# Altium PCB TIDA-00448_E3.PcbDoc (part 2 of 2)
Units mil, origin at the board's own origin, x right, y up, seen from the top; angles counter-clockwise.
Board outline 2125 x 2550 mil, 4 copper layers (Top Layer, MidLayer1, MidLayer2, Bottom Layer), stack 90 mil thick; 140 components, 62 nets, 330 pads, 116 vias.
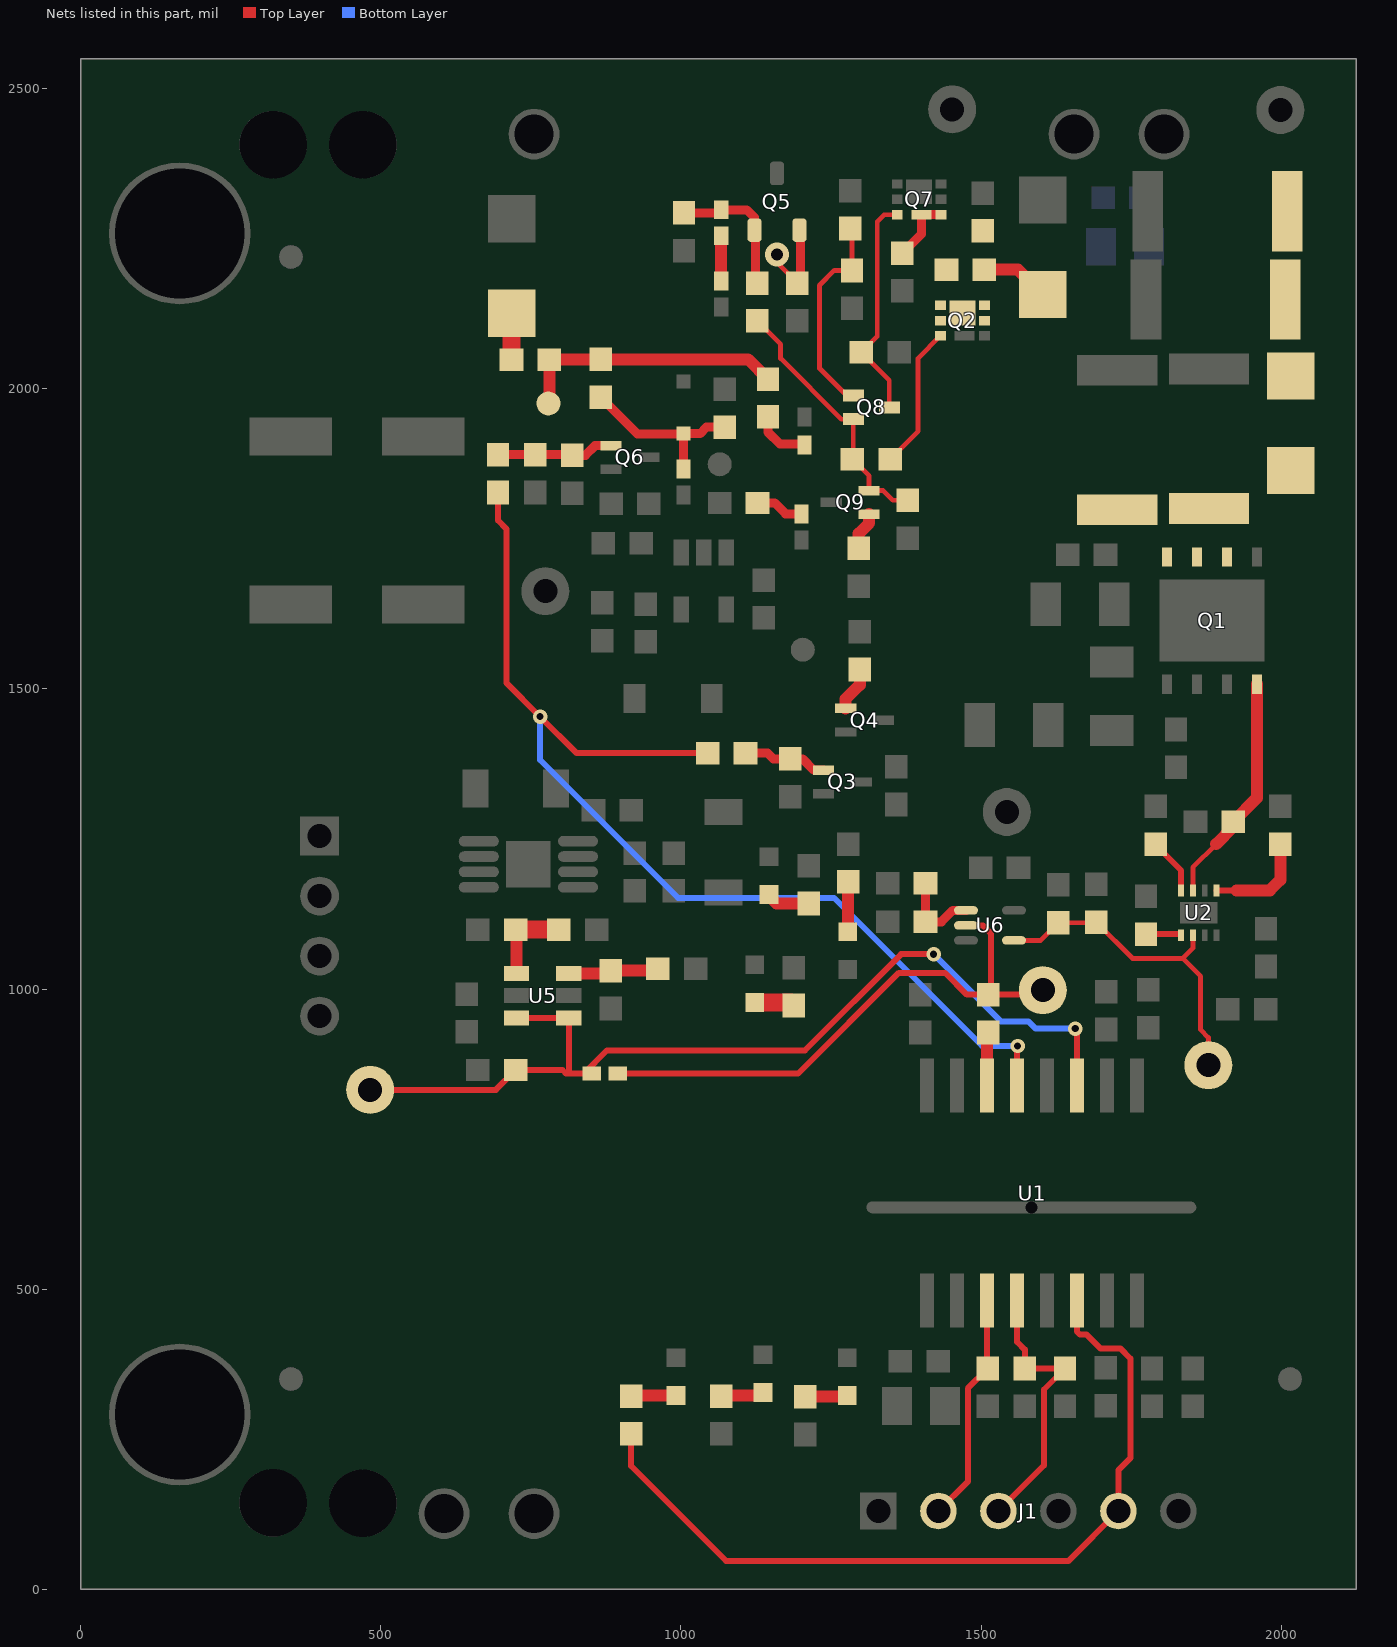
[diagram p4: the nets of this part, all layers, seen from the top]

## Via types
v1: diameter 30, hole 16, Top Layer to Bottom Layer, tented both sides, 89 vias
v2: diameter 24, hole 12, Top Layer to Bottom Layer, 26 vias
v3: diameter 40, hole 20, Top Layer to Bottom Layer, 1 vias

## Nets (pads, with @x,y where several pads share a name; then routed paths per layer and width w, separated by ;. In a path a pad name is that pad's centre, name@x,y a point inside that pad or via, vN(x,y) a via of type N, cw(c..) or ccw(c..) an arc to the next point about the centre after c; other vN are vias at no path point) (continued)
NetC24_2: C24.2 Q6.1 R15.2 R39.1 | length 195.6
  Top Layer w15: R15.2@695,1890.5 R39.1@757,1890.5 818,1890.5 C24.2@819,1889.5 840.5,1889.5 856.68,1905.68 Q6.1@883.5,1905.68
NetC39_1: C39.1 D7.2 Q5.1 R13.1 | length 235.2
  Top Layer w15: C39.1@1005,2293.5 1061.84,2293.5 D7.2@1067,2298.65 1109.35,2298.65 1122.6,2285.4 Q5.1@1122.6,2264.76 ; Q5.1@1124.6,2264.76 1124.6,2258.76 1124.5,2258.66 1124.5,2179 R13.1@1127,2176.5
NetC41_2: C41.2 R60.2 U6.1 | length 139.4
  Top Layer w15: R60.2@1407.5,1176 C41.2@1407.5,1112 1434,1112 1453,1131 U6.1@1475,1131
NetD1_2: D1.2 R2.2 R58.2
NetD2_2: D2.2 R6.1 | length 77.5
  Top Layer w30: R6.1@717.5,2049 717.5,2125.76 D2.2@718,2126.26
NetD5_2: D5.2 D20.1 R9.1 R11.2 | length 296.8
  Top Layer w15: R9.1@866,1986.5 927.81,1924.69 D20.1@1000,1924.69 ; D5.2@1004,1866.65 1004,1920.69 D20.1@1000,1924.69 ; D20.1@1004,1924.69 D20.1@1000,1924.69 ; D20.1@1004,1925.69 1031.69,1925.69 1042.5,1936.5 R11.2@1073,1936.5
NetD6_1: D6.1 R14.2 | length 81.1
  Top Layer w15: R14.2@1127.5,1810 1156,1810 1174.35,1791.65 D6.1@1201,1791.65
NetD7_1: D7.1 D17.2 | length 75.7
  Top Layer w20: D17.2@1067,2179.65 D7.1@1067,2255.35
NetD9_1: D9.1 R42.2 | length 76.2
  Top Layer w20: D9.1@1143,1157.5 1144.5,1157.5 1159.5,1142.5 R42.2@1213,1142.5
NetD10_1: D10.1 R43.1 | length 67.1
  Top Layer w30: D10.1@1123,977.5 1183,977.5 R43.1@1188,972.5
NetD11_1: D11.1 R44.2 | length 83.4
  Top Layer w20: D11.1@1278,1095.5 1278,1177.5 R44.2@1279,1178.5
NetD12_1: D12.1 R45.2 | length 70.8
  Top Layer w20: R45.2@1207,320.5 1274.99,320.5 D12.1@1277,322.5
NetD13_1: D13.1 R46.2 | length 75
  Top Layer w20: R46.2@917,322.5 D13.1@992,322.5
NetD14_1: D14.1 R47.2 | length 72.1
  Top Layer w20: R47.2@1067,322.5 1132,322.5 D14.1@1137,327.5
NetD18_2: D18.2 R31.2 | length 114.8
  Top Layer w20: R31.2@1505.5,2199 1561.26,2199 D18.2@1603,2157.26
NetQ2_1: Q2.1 Q2.2 Q2.5 Q2.6 Q2.8 R5.1 R31.1
NetQ2_3: Q2.3 R59.1 | length 240.2
  Top Layer w8: R59.1@1348.5,1883 1395.18,1929.69 1395.18,2051.2 Q2.3@1432.39,2088.41
NetQ3_1: Q3.1 R52.2 R53.1 | length 141.7
  Top Layer w15: R52.2@1107.5,1393 1144.46,1393 1153.96,1383.5 R53.1@1182,1383.5 1202.5,1383.5 1221.32,1364.68 Q3.1@1237.5,1364.68
NetQ4_1: Q4.1 R10.2 | length 74.6
  Top Layer w20: Q4.1@1274.5,1467.68 1274.5,1483.5 1298,1507 R10.2@1298,1532.5
NetQ5_2: Q5.2 R16.2 | length 146.1
  Top Layer w8: v3(1160,2224) 1166,2218 1166,2204.5 R16.2@1194,2176.5
  Top Layer w15: R16.2@1194,2176.5 1199.4,2181.9 Q5.2@1199.4,2258.76
NetQ7_3: Q7.3 Q8.3 R17.2 | length 378
  Top Layer w8: Q8.3@1347.2,1969.4 1347.2,2014.3 R17.2@1300.5,2061 1327,2087.5 1327,2279 1338.41,2290.41 Q7.3@1360.39,2290.41
NetQ7_4: Q7.4 Q7.7 R50.2 | length 109.9
  Top Layer w15: R50.2@1369,2226.5 1400.74,2258.24 Q7.7@1400.74,2290.41 Q7.4@1433.61,2290.41
NetQ8_1: Q8.1 R18.2 R19.2 | length 349.3
  Top Layer w8: R18.2@1282,2267.5 1285,2264.5 R19.2@1285,2197.5 1255.5,2197.5 1230.82,2172.82 1230.82,2034.18 1275.9,1989.1 Q8.1@1287.2,1989.1
NetQ8_2: Q8.2 Q9.2 R13.2 R32.2 R59.2 | length 444.4
  Top Layer w8: R13.2@1127,2113.5 1166,2074.5 1166,2050.85 1267.15,1949.7 Q8.2@1287.2,1949.7 1287.2,1884.7 R59.2@1285.5,1883 1313.5,1855.01 Q9.2@1313.5,1830.69 1337.05,1830.69 1353.24,1814.5 R32.2@1378,1814.5
NetQ9_1: Q9.1 R51.2 | length 64.1
  Top Layer w20: R51.2@1296,1734.5 1296,1759 1313.5,1776.5 Q9.1@1313.5,1791.32
NetR1_2: R1.2 U2.1 | length 59.3
  Top Layer w10: R1.2@1775,1091.5 1831.57,1091.5 U2.1@1833.47,1089.6
NetR6_2: R6.2 R8.2 R9.2 TP5.1 | length 452
  Top Layer w20: TP5.1@779,1976 780.5,1977.5 R6.2@780.5,2049 865.5,2049 R9.2@866,2049.5 1112,2049.5 R8.2@1145,2016.5
NetR8_1: R8.1 R34.2 | length 94.6
  Top Layer w15: R8.1@1145,1953.5 1145,1928 1164.65,1908.35 R34.2@1206,1908.35
NetR22_1: R22.1 U2.8 | length 94.7
  Top Layer w10: R22.1@1791,1241.5 1791,1240 1833.47,1197.53 U2.8@1833.47,1164.4
NetR26_1: R26.1 U2.5 | length 173.3
  Top Layer w10: U2.5@1892.53,1164.4 1925.4,1164.4
  Top Layer w20: 1925.4,1164.4 1981.4,1164.4 1999,1182 R26.1@1999,1241.5
NetR33_1: R33.1 R36.2 U5.4 | length 145.6
  Top Layer w20: U5.4@726,1026 R33.1@726,1097.5
  Top Layer w30: R33.1@726,1097.5 R33.1@724.5,1099 R36.2@796.5,1099
NetR35_1: R35.1 R37.2 U5.3 | length 151.8
  Top Layer w20: U5.3@813,1026 878.5,1026 R37.2@883,1030.5 958,1030.5 R35.1@961.5,1034
NetR41_2: R41.2 U1.14 | length 89.2
  Top Layer w20: U1.14@1510,839.13 1510,925.5 R41.2@1512,927.5
PWM: J1.2 R23.1 U1.3 | length 383.8
  Top Layer w10: J1.2@1429,130 1478,179 1478,334.5 R23.1@1511,367.5 ; R23.1@1510,368.5 U1.3@1510,480.87
PWM-ISO: D8.2 R41.1 TP10.1 U6.2 | length 947.5
  Top Layer w10: D8.2@894.65,859 1195,859 1363,1027 1440,1027 1476.5,990.5 R41.1@1512,990.5 ; U6.2@1475,1106 1503,1106 1517,1092 1517,995.5 R41.1@1512,990.5 ; TP10.1@1603,998 1595.5,990.5 R41.1@1512,990.5
PWM_BUF: R56.2 R57.1 TP9.1 U2.2 U6.4 | length 560.2
  Top Layer w8: U6.4@1555,1081 1599.5,1081 R57.1@1629,1110.5 1691,1110.5 R56.2@1692,1111.5 1752.5,1051 1836,1051 ; U2.2@1853.16,1089.6 1853.16,1068.16 1836,1051 ; TP9.1@1879,873 1879,919 1866,932 1866,1021 1836,1051
RESET: C23.2 J1.3 R25.1 U1.4 | length 492.4
  Top Layer w10: J1.3@1529,130 1605,206 1605,332.5 R25.1@1640,367.5 C23.2@1573,367.5 1573,399 1560,412 U1.4@1560,480.87 ; 1612.8,367.5 R25.1@1636,367.5
RESET-ISO: R15.1 R52.1 U1.13 | length 1839
  Top Layer w10: R15.1@695,1827.5 695,1781 709,1767 709,1510.12 v2(765.12,1454) 826.12,1393 R52.1@1044.5,1393 ; U1.13@1560,839.13 1560,904 v2(1561,905)
  Bottom Layer w10: v2(765.12,1454) 765.12,1381.88 995,1152 1255,1152 1502,905 v2(1561,905)
SW: C5.2 Q1.4 U2.7 | length 387.9
  Top Layer w8: U2.7@1853.16,1164.4 1853.16,1202.81 1891.85,1241.5
  Top Layer w20: 1891.85,1241.5 1920.5,1270.15 C5.2@1920.5,1279 1960,1318.5 Q1.4@1960,1508
SW-A: D1.1 Q1.6 Q1.7 Q1.8 R3.1 R55.1
U\V\L\O\: J1.5 R46.1 U1.6 | length 1387.3
  Top Layer w10: R46.1@917,258.5 917,205 1075,47 1646,47 J1.5@1729,130 1729,198 1749,218 1749,384.27 1732.09,401.18 1698.82,401.18 1676,424 1665,424 1660,429 U1.6@1660,480.87
U\V\L\O\-\I\S\O\: D8.1 R30.1 TP7.1 U1.11 U5.1 U5.6 | length 1602.9
  Top Layer w10: TP7.1@482,832 691.5,832 R30.1@724.5,865 802.53,865 808.53,859 ; U5.6@726,952 U5.1@813,952 813,863.47 808.53,859 ; v2(1421,1058) 1367,1058 1206.5,897.5 876.5,897.5 838,859 808.53,859 ; v2(1657,934) 1660,931 U1.11@1660,839.13
  Bottom Layer w10: v2(1421,1058) 1533,946 1579.04,946 1591.04,934 v2(1657,934)
pads on no net: FID1.1 FID2.1 FID3.1 FID4.1 FID5.1 FID6.1 LBL1.0 M1. U4.3 U4.6 U4.7

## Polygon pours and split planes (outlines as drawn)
0V on Bottom Layer "Top Layer-No Net" (solid, remove dead copper, pour order 25): 1520,2449 1520,2000 1547.67,1972.33 1705.33,1972.33 1723,1990 1723,2457 1716,2464 1535,2464
+15V on Bottom Layer "Top Layer-No Net" (solid, remove dead copper, pour order 34): 531,1543 543.78,1530.22 1308,1531 1489,1349 1887,1349 1902,1364 1902,1508 1884,1526 1594,1526 1325,1795 547,1795 531,1779
GND on Bottom Layer "Bottom Layer-No Net 1" (solid, remove dead copper, pour order 39): 874,35 841,68 841,473 861,493 1926,493 1956,463 1956,61 1930,35
0V on Top Layer "Top Layer-No Net 1" (solid, remove dead copper, pour order 38): 1860,1381 1860,1352 1846,1338 1470,1338 1455,1353 1455,1720 1497,1762 1497,2020 1536,2059 1649,2059 1659,2049 1659,1769 1678,1750 1678,1697 1652,1671 1652,1526 1628,1502 1577,1502 1561,1486 1561,1400 1566,1395 1846,1395
+15V on Top Layer "Top Layer-No Net 1" (solid, remove dead copper, pour order 36): 1580,1482 1580,1435 1580,1407 1586,1401 1588,1399 1658,1399 1881,1399 1889,1407 1889,1517 1889,1523 1885,1527 1848,1527 1801,1527 1793,1519 1755,1481 1717,1481 1589,1481 1580,1472
SW-A on Top Layer "Top Layer-No Net 1" (solid, remove dead copper, pour order 33): 1962,1920 2064,1920 2070,1920 2081,1909 2085,1905 2085,1827 2085,1776 2072,1763 2057,1748 1948,1748 1946.92,1748 1933,1734.08 1932,1733.08 1932,1715 1932,1709 1921,1698 1920,1697 1896,1697 1801,1697 1796,1702 1785,1713 1785,1750 1785,1753 1774,1764 1771,1767 1726,1767 1669,1767 1663,1767 1658,1772 1657,1773 1657,1818 1657,1908 1669,1920
-8V on Top Layer "Top Layer-No Net 1" (solid, remove dead copper, pour order 29): 1691,1746 1686,1741 1682.57,1737.57 1682.57,1554.93 1682.57,1520.43 1684,1519 1686,1517 1718,1517 1758,1517 1760,1519 1780.67,1539.67 1780.67,1541.91 1843.09,1541.91 1972.91,1541.91 1977,1546 1980,1549 1980,1571 1980,1678 1975,1683 1952,1683 1796,1683 1774,1683 1767,1690 1766,1691 1766,1720 1766,1742 1762,1746
NetD1_2 on Top Layer "Top Layer-No Net 1" (solid, remove dead copper, pour order 27): 1974,2366 1974,2272 1974,2204 1974,1983 1977,1980 1980,1977 2026,1977 2080,1977 2085,1982 2088,1985 2088,2038 2088,2369 2084,2373 2076,2381 1991,2381 1980,2381 1974,2375
0V on Top Layer "Top Layer-No Net" (solid, remove dead copper, pour order 30): 233,1136 253,1116 413,1116 428,1131 428,1181 408,1201 369,1201 346,1224 346,1446 435,1535 435,1970 417,1988 242,1988 233,1979
-8V on Top Layer "Top Layer-No Net" (solid, remove dead copper, pour order 24): 710,1262.82 710,1202 710,1160.22 713.87,1156.35 714.67,1155.55 773.57,1155.55 782.75,1155.55 789.48,1162.28 789,1162.77 789,1186 789,1225.23 795.22,1231.45 804.28,1240.51 842.19,1240.51 867.51,1240.51 871,1244 873,1246 873,1283 873,1356 858,1371 809,1371 772,1371 766,1365 761,1360 761,1336 761,1279 756,1274 751,1269 716,1269
+15V on Top Layer "Top Layer-No Net" (solid, pour order 21): 361,1222 364,1219 440,1219 511,1148 556,1148 556,1553 578,1553 578,1148 689,1148 699,1158 699,1268 690,1277 690,1284 690,1285 690,1441 690,1546 690,1738 673,1755 484,1755 466,1737 466,1521 361,1416
-8V on Top Layer "Top Layer-No Net" (solid, remove dead copper, pour order 28): 549,1978 549,1813 558,1804 656,1804 665,1813 665,1977.73 659.73,1983 554,1983
GATE on Top Layer "Top Layer-No Net 1" (solid, remove dead copper, pour order 23): 1141,2404 1141,2315 1149,2307 1525,2307 1589,2243 1646,2243 1659,2230 1659,2006 1667,1998 1945,1998 1952,2005 1952,2065 1947,2070 1889,2070 1876,2083 1876,2443 1841,2478 1771,2478 1753,2460 1753,2399 1731,2377 1330,2377 1294,2413 1150,2413
NetQ2_1 on Top Layer "Top Layer-No Net" (solid, remove dead copper, pour order 22): 1480,2286 1517,2286 1523,2286 1526,2283 1530.2,2278.8 1530.2,2261 1530.2,2240.2 1522,2232 1516,2226 1480,2226 1470,2226 1464,2220 1464,2193 1464,2175 1471,2168 1475,2164 1496,2164 1519.39,2164 1525.1,2158.29 1525.1,2114 1525.1,2110.1 1519,2104 1481,2104 1422.9,2104 1412.9,2114 1412,2114.9 1412,2136 1412,2231 1417,2236 1421,2240 1467,2286 1474,2286
0V on MidLayer1 "Top Layer-No Net" (solid, remove dead copper, pour order 31): 239.97,1697.71 254.97,1682.71 419.97,1682.71 429.97,1692.71 429.97,1962.71 450.27,1983 1891,1983 1909.97,2001.97 1909.97,2175.71 1904.68,2181 493.27,2181 414.97,2102.71 249.97,2102.71 239.97,2092.71
-8V on MidLayer1 "Top Layer-No Net" (solid, remove dead copper, pour order 32): 549,1814 559,1804 1346,1804 1608,1542 1973,1542 1992,1561 1992,1796 1968,1820 1774,1820 1631,1963 559,1963 549,1953
"3.3V/ 5V" on MidLayer1 "Bottom Layer-No Net 1" (solid, remove dead copper, pour order 37): 874,35 841,68 841,473 861,493 1926,493 1956,463 1956,61 1930,35
-3V on MidLayer1 "Top Layer-No Net" (solid, remove dead copper, pour order 26): 601,1049 670,1049 710,1089 710,1719 735,1744 1305,1744 1323,1726 1323,1381 1365,1339 2010,1339 2040,1309 2040,859 2030,849 607,849 595,861 595,1043
-8V on MidLayer2 "Top Layer-No Net" (solid, remove dead copper, pour order 40): 284.42,1983.38 284.42,1763.58 308.42,1739.58 562.42,1739.58 578,1724 578,862 621,819 2076,819 2094.99,837.99 2094,2356 2094,2357 2078,2373 1070,2373 863.89,2166 530.01,2166 378.42,2014.58 323.42,2014.58
-8V on MidLayer2 "Top Layer-No Net" (solid, remove dead copper, pour order 35): 555.66,909.56 546.66,900.56 275.45,900.56 265.66,910.35 265.66,1965.56 285.66,1985.56 295.66,1985.56 545.17,1986.06 555.66,1975.56

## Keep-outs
Keep-Out Layer:
  lines w8: 29,25 2095,25 2095,2525 29,2525 29,25
  text ".Layer_Name" at -608,-1463.49 h60

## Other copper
Top Layer:
  text ".Layer_Name" at -608,-1463.49 h60
MidLayer1:
  text "2.2" at 531,231 h80
  text ".layer_Name" at -637,-1453 h60
MidLayer2:
  pour cut-out: 1780.67,1686.09 1781,1685.76 1781,1529.33 1780.67,1529 1988.65,1529 1989.33,1528.32 1990,1528.99 1990,1699.01 1989.01,1700 1780.99,1700 1780.67,1699.68
  text ".layer_Name" at -637,-1453 h60
Bottom Layer:
  text ".Layer_Name" at -608,-1463.49 h60

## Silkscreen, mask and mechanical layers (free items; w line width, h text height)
Top Overlay:
  circle w6: c1338,1774 r4.47
  circle w6: c1203,1565.5 r26.63
  circle w6: c1064.5,1874.5 r26.63
  circle w6: c779,1976 r26.63
  circle w10: c856.76,1933 r4.24
  circle w10: c1270,2021 r2.24
  circle w6: c1408.5,2160 r2.5
  circle w10: c1331,2362 r2.24
  circle w6: c1012,2450 r25
  circle w6: c1932.75,400 r30
  circle w6: c1964.75,649 r30
  circle w10: c860,918 r3.61
  circle w10: c872,1158 r2
  circle w10: c1830.17,1053 r5.83
  circle w10: c1783.6,1481 r6.4
  circle w10: c1103.29,1725 r6.71
  circle w6: c1348,462 r8.06
  circle w10: c1239,1393 r3.16
  circle w10: c1289,1491 r3.16
  circle w6: c1131,1884 r25
  lines w6: 26,735 45,735 1001,735 ; 631,1054 676,1054 ; 678,1786 678,1791 ; 734,1776 744.99,1786.99 747,1786.99 ; 820,1720 ccw(c832.07,1720) 823.54,1711.46 832.76,1702.24 ccw(c843,1712.49) 843,1698 ; 820,1724 820,1729 820,1730 ; 839,1359 840,1358 840,1338 ; 844,1699 955,1699 966,1699 969,1702 969,1725 970,1726 970,1757 983,1770 1088,1770 ; 852,1845 959,1845 971,1857 971,1861 ; 952,1980 952,2038 971,2038 1075,2038 1092,2055 1176,2055 1181,2050 1181,2013 ; 958.98,1966.99 958.98,1925 ; 974,1269 974,1324 967,1317 980,1317 974,1323 ; 1166.73,2082 1092,2082 972,2082 910,2144 ; 1170.31,1779.99 1171,1780.67 1171,1868 1177,1874 1177,1918 ; 1239,2361 1239,2201 1249,2191 1249,2184 ; 1312,733 2107,733 ; 1313,1250 1345,1250 1355,1240 1390,1240 ; 1315,2006 1324,2006 ; 1317,1934 1326,1934 1327,1935 1327,1942 ; 1318,361 1318,527 ; 1325,1995 1325,2006 ; 1398,2121 1398,2094 1402,2090 1402,2072 ; 1428,1311 1432,1307 1432,1212 ; 1450,2232 1450,2240 1463,2253 1463,2363 ; 1474,363 1474,409 1861,409 1891,409 1891,275 1884,268 1487,268 ; 1582,1353 1619,1353 1632,1366 ; 1810,1190 1839,1190 1855,1206 1860,1206 ; 1925,1763 1960,1763 1995,1728 2018,1728 2026,1720 ; 910,2144 918,2144 920,2142 ; 910,2144 912,2142 920,2142 ; 910,2144 910,2132 920,2142 ; 958.98,1925 959,1924.98 ; 688,917 688,1062 848,1062 848,917 688,917 ; 790,2246 791,2245 903,2245 904,2246 904,2318 906,2320 958,2320 974,2336 974,2378 974,2510 970,2514 826,2514 814,2514 812,2512 812,2500 812,2370 795,2353 795,2352 790,2347 790,2246 ; 1817,492 1817,609 2063,609 2072,600 2072,492 2065,492 1817,492
  lines w10: 1318,527 1307,516 1331,516 1320,527
  text "b" at 1003,2435 h30
  text "b" at 1122,1869 h30
  text "Isolation" at 1011,721 h35
  text "A" at 1951,633 h35
  text "TIDA-00448-E3" at 347,455 h80
  text "A" at 1919,384 h35
  text ".Layer_Name" at -608,-1463.49 h60
Bottom Overlay:
  text ".Layer_Name" at -557,-1457 h60
Top Paste:
  text ".Layer_Name" at -608,-1463.49 h60
Bottom Paste:
  text ".Layer_Name" at -608,-1463.49 h60
Top Solder:
  text ".Layer_Name" at -608,-1463.49 h60
  text ".Layer_Name" at -608,-1463.49 h60
Bottom Solder:
  text ".Layer_Name" at -608,-1463.49 h60
Drill Guide:
  text ".Layer_Name" at -608,-1463.49 h60
M1 Board Outline:
  the board outline again, w10
M2 Board Dimensions:
  rectangle: -1185.5,-890.5 -1060.5,-765.5
  rectangle: -1060.5,-1015.5 -685.5,-890.5
  lines w7: -1185.5,-890.5 -185.5,-890.5 ; -1060.5,-1015.5 -1060.5,-765.5 ; -935.5,-1015.5 -935.5,-765.5 ; -685.5,-1015.5 -685.5,-765.5 ; -435.5,-1015.5 -435.5,-765.5 ; -1185.5,-1015.5 -185.5,-1015.5 -185.5,-765.5 -1185.5,-765.5 -1185.5,-1015.5
  lines w10: -1185.5,-1080.5 -1185.5,-1060.5 ; -1125.5,-1090.5 -1185.5,-1070.5 ; -1125.5,-1050.5 -1185.5,-1070.5 ; -961.42,-1070.5 -1185.5,-1070.5 ; -409.58,-1070.5 -185.5,-1070.5 ; -245.5,-1090.5 -185.5,-1070.5 ; -245.5,-1050.5 -185.5,-1070.5 ; -185.5,-1080.5 -185.5,-1060.5
  text "1000 (mil)" at -951.42,-1106.49 h60
M3 3D STEP Top:
  text ".Layer_Name" at -608,-1463.49 h60
M4 3D STEP Bottom:
  text ".Layer_Name" at -608,-1463.49 h60
M5 Assembly Top:
  circle w6: c1329,130 r12.08
  circle w6: c1207,1611.5 r23.03
  circle w6: c780.5,1977.5 r23.03
  circle w6: c1064.5,1874.5 r23.03
  circle w10: c1273,2001 r7.28
  circle w10: c1286,1791 r3.16
  circle w10: c911,1904 r2
  circle w10: c397.75,1254.8 r22.19
  circle w6: c1270.79,1363 r7.21
  circle w6: c1468.79,1155 r7.21
  circle w6: c1306.79,1466 r7.21
  circle w6: c1076.79,1697 r7.21
  circle w6: c1123.79,2297 r7.21
  lines w10: -1477,-1535.17 5123,-1535.17 ; -1477,-1331.83 5125,-1331.83 ; -1477,-1128.5 -1477,-1738.5 2528,-1738.5 5125,-1738.5 5125,-1128.5 -1476.5,-1128.5 -1476.5,-1738.5 99,-1738.5 ; 988,-1738.5 988,-1128.5 ; 2255,-1331.83 2255,-1128.5 ; 3095,-1331.83 3095,-1128.5 ; 3717,-1745 3717,-1542.17
  text "TP5" at 665,1977.73 h30
  text "TP6" at 1094,1855 h30
  text "TP8" at 1173,1542 h30
  text "COMPONENTS MARKED 'DNP' SHOULD NOT BE POPULATED." at -31.5,-923.5 h35
  text "ASSEMBLY VARIANT:" at -32,-1039 h35
  text ".VariantName" at 1004,-1039 h35
  text "PCB VIEWED FROM TOP SIDE" at -1413.5,-1260.67 h35
  text "BOARD #:" at 1063,-1260.67 h35
  text ".prj_number" at 1523,-1261 h35
  text "REV:" at 2453,-1260.67 h35
  text ".PCB_Rev" at 2744.5,-1260.67 h35
  text "SVN REV:" at 3291,-1260.67 h35
  text ".VersionControl_RevNumber" at 3797,-1260.67 h35
  text "IGNORE ->" at -1413.5,-1463.49 h35
  text "ASSEMBLY TOP" at -595,-1469 h35
  text "PLOT NAME =" at -1413.5,-1669.34 h35
  text ".plot_File_Name" at -608,-1669.34 h35
  text "GENERATED    :" at 1065,-1669.34 h35
  text ".Print_Date" at 1934.5,-1669.34 h35
  text ".Print_Time" at 2663.5,-1669.34 h35
  text "TEXAS INSTRUMENTS" at 3928,-1669.34 h35
M6 Assembly Bottom:
  lines w10: -1477.5,-1332.33 5124.5,-1332.33 ; -1475.5,-1535.67 5124.5,-1535.67 ; -69.5,-1745.5 -69.5,-1542.67 ; 552.5,-1332.33 552.5,-1129 ; 1392.5,-1332.33 1392.5,-1129 ; 2659.5,-1739 2659.5,-1129 ; 3548.5,-1739 5124,-1739 5124,-1129 -1477.5,-1129 -1477.5,-1739 1119.5,-1739 5124.5,-1739 5124.5,-1129
  text "COMPONENTS MARKED 'DNP' SHOULD NOT BE POPULATED." at 4917,-923 h35
  text ".VariantName" at 3873,-1039 h35
  text "ASSEMBLY VARIANT:" at 4912,-1039 h35
  text ".VersionControl_RevNumber" at -149.5,-1261.17 h35
  text "SVN REV:" at 356.5,-1261.17 h35
  text ".PCB_Rev" at 903,-1261.17 h35
  text "REV:" at 1194.5,-1261.17 h35
  text "BOARD #:" at 2584.5,-1261.17 h35
  text "PCB VIEWED FROM BOTTOM SIDE" at 5061,-1261.17 h35
  text ".prj_number" at 2224,-1262 h35
  text "IGNORE ->" at 1362.85,-1463.49 h35
  text "ASSEMBLY BOTTOM" at 276,-1469 h35
  text "TEXAS INSTRUMENTS" at -280.5,-1669.84 h35
  text ".Print_Time" at 984,-1669.84 h35
  text ".Print_Date" at 1713,-1669.84 h35
  text "GENERATED    :" at 2582.5,-1669.84 h35
  text ".plot_File_Name" at 4255.5,-1669.84 h35
  text "PLOT NAME =" at 5061,-1669.84 h35
M9 Title Sheet:
  drawing of 57 lines, arcs and shapes, not listed
  text "1" at -445.16,7431.5 h70
  text "2" at 2050.5,7431.5 h70
  text "3" at 4539.84,7431.5 h70
  text "4" at 7046.51,7431.5 h70
  text "5" at 9545.5,7431.5 h70
  text "6" at 12050.5,7431.5 h70
  text "A" at -1601.5,6288.5 h70
  text "A" at 13198.5,6288.5 h70
  text "B" at -1601.5,3908.5 h70
  text "B" at 13198.5,3908.5 h70
  text "C" at -1601.5,1533.5 h70
  text "C" at 13198.5,1533.5 h70
  text "PROJECT TITLE:" at 10158.5,-327.5 h45
  text ".PRJ_Title" at 10208.5,-460.83 h70
  text "DESIGNED FOR:" at 10158.5,-628.5 h45
  text ".PRJ_Customer" at 10208.5,-768.5 h70
  text "D" at -1601.5,-836.5 h70
  text "D" at 13198.5,-836.5 h70
  text "FILE NAME:" at 10158.5,-928.5 h45
  text ".PCB_File_Name_No_Path" at 10208.5,-1048.5 h70
  text "Texas Instruments (TI) and/or its licensors do not warrant the accuracy or completeness of this specification" at 5189,-1210.34 h45
  text "ENGINEER:" at 10158.5,-1218.5 h45
  text "LAYOUT BY:" at 11663.5,-1218.5 h45
  text "or any information contained therein. TI and/or its licensors do not warrant that this design will meet" at 5144.01,-1323 h45
  text ".PRJ_Engineer" at 10208.5,-1373.49 h70
  text "Manjunatha T N" at 11714,-1373.49 h70
  text "the specifications, will be suitable for your application or fit for any particular purpose, or will operate in" at 5144.01,-1435.67 h45
  text "ALTIUM DESIGNER VERSION:" at 11663.5,-1528.5 h45
  text "an implementation. TI and/or its licensors do not warrant that the design is production worthy. You should" at 5144.01,-1548.33 h45
  text "completely validate and test your design implementation to confirm the system functionality for your application." at 5189,-1661 h45
  text ".print_Scale" at 10208.5,-1661.83 h70
  text ".Application_BuildNumber" at 11714,-1661.83 h70
  text "1" at -445.16,-1868.5 h70
  text "2" at 2050.5,-1868.5 h70
  text "3" at 4539.84,-1868.5 h70
  text "4" at 7046.51,-1868.5 h70
  text "5" at 9545.5,-1868.5 h70
  text "6" at 12050.5,-1868.5 h70
M10 Fab Notes:
  drawing of 228 lines, arcs and shapes, not listed
  text "DESIGN INFORMATION" at 11196.02,6205 h60
  text "(REFER ALSO ARRAY/PANEL PROFILING INFORMATION)" at 10834.46,6043.29 h60
  text "BOARD SIZE" at 10148.46,6039 h60
  text "53.98MM" at 10610.78,5911.18 h60
  text "X" at 11116.46,5911.18 h60
  text "64.77MM" at 11347.78,5911.18 h60
  text "Number of Layers :" at 10551.46,5714 h60
  text "4" at 11646.27,5704 h60
  text "MIN. TRACK WIDTH:" at 10551.46,5575 h60
  text "8" at 11620,5575 h60
  text "MIL" at 11802.46,5575 h60
  text "MIN. CLEARANCE:" at 10551.46,5443 h60
  text "MIL" at 11802.46,5443 h60
  text "7.874" at 11506,5440 h60
  text "MIN. VIA PAD SIZE:" at 10551.46,5311 h60
  text "24" at 11617.71,5311 h60
  text "MIL" at 11802.46,5311 h60
  text "0.152mm (6MIL)" at 11268,5169 h60
  text "MINIMUM ANNULAR RING" at 10222.23,5165 h60
  text "EXTERNAL" at 12020,5165 h60
  text "PER" at 10422.23,5047 h60
  text "IPC-D-275 CLASS 2 LEVEL C" at 10642.23,5047 h60
  text "MIL, HOLES" at 12130.46,4934.71 h60
  text "+/-" at 11738,4934 h60
  text "+/-" at 12592,4934 h60
  text "REGISTRATION TOLERANCES:" at 10222.23,4929 h60
  text "METAL" at 11422,4929 h60
  text "5" at 11998.2,4929 h60
  text "3" at 12831.2,4929 h60
  text "MIL" at 12947.46,4929 h60
  text "MATERIAL:" at 10147.46,4719.54 h60
  text "FR-4 High Tg" at 11133.9,4579.21 h60
  text "X" at 10973,4573 h60
  text "FR-408" at 10568.46,4570.64 h60
  text "OTHER" at 12056.46,4570.64 h60
  text "63 MIL (1.6mm) +/-10%" at 10888.56,4407.92 h60
  text "THICKNESS:" at 10222.23,4403.64 h60
  text "X" at 10760.4,4403.64 h60
  text "OTHER" at 12173.46,4403.64 h60
  text "TOLERANCE:" at 10222.23,4245.64 h60
  text "X" at 11061.53,4245.64 h60
  text "ANSI IPC-6012 TYPE 3 CLASS 2" at 11248.48,4245.64 h60
  text "OTHER +/-" at 11248.46,4089.64 h60
  text "BOW & TWIST:" at 10222.23,3932.64 h60
  text "X" at 11061.53,3932.64 h60
  text "ANSI IPC-6012 TYPE 3 CLASS 2" at 11248.48,3932.64 h60
  text "OTHER +/-" at 11248.46,3774.13 h60
  text "COPPER THICKNESS (FINISHED):" at 10147.46,3638.64 h60
  text "1.4MIL (1oz)" at 11027.46,3485.92 h60
  text "2MIL (1.4oz)" at 11794.46,3485.92 h60
  text "2.8MIL (2oz)" at 12521.46,3485.92 h60
  text "OUTER:" at 10504.46,3481.64 h60
  text "X" at 10899,3481 h60
  text "1.4MIL (1oz)" at 11027.46,3328.92 h60
  text "2.8MIL (2oz)" at 11794.46,3328.92 h60
  text "N/A" at 12521,3329.29 h60
  text "INNER SIGNAL:" at 10215.38,3324.64 h60
  text "X" at 10899,3324 h60
  text "DRILLING:" at 10147.46,3185.64 h60
  text "REFERENCE:" at 10222.23,3068.64 h60
  text "X" at 10870.46,3068.64 h60
  text "AS SHOWN" at 11057.46,3068.64 h60
  text "X" at 11771.46,3068.64 h60
  text "NC_DRILL FILES" at 11908.46,3068.64 h60
  text "NOTES:" at 6448,2992 h80
  text "PTH MIN COPPER THICKNESS:" at 10222.23,2910.64 h60
  text "X" at 11572.46,2910.64 h60
  text "1MIL" at 11709.46,2910.64 h60
  text "OTHER" at 12206.46,2910.64 h60
  text "20MIL via not Tented." at 6444,2874 h60
  text "12MIL vias are not Tented." at 6443,2763 h60
  text "BOARD FINISH:" at 10147.46,2751.64 h60
  text "X" at 11756.46,2638.64 h60
  text "SILKSCREEN:" at 10302.68,2633.64 h60
  text "X" at 11251.46,2633.64 h60
  text "TOP" at 11377.46,2633.64 h60
  text "BOTTOM" at 11888.46,2633.64 h60
  text "16MIL vias are Tented both the sides" at 6454,2630 h60
  text "SILKSCREEN COLOR:" at 10302.68,2466.64 h60
  text "X" at 11250.42,2466.64 h60
  text "WHITE" at 11377.46,2466.64 h60
  text "OTHER" at 11888.46,2466.64 h60
  text "SOLDER RESIST COLOR:" at 10302.68,2296.64 h60
  text "X" at 10870.42,2137.44 h60
  text "GREEN" at 10997.46,2137.44 h60
  text "BLUE" at 11588.46,2137.44 h60
  text "OTHER" at 12126.46,2137.44 h60
  text "IMMERSION GOLD (ENIG)" at 11208.46,1948.92 h60
  text "ENEPIG" at 12546,1945.64 h60
  text "SURFACE FINISH:" at 10147.46,1944.64 h60
  text "X" at 11021.51,1944.64 h60
  text "IMM. TIN/SILVER OR EQUIV" at 10477,1787.64 h60
  text "OTHER" at 11908.46,1787.64 h60
  text "ARRAY/PANEL:" at 10147.46,1608.64 h60
  text "CUT AND TRIM PER MECH LAYER 1" at 11208.46,1604.35 h60
  text "N.C. ROUTE" at 11208.46,1452.64 h60
  text "X" at 11887.46,1452.64 h60
  text "V. SCORE" at 12074.46,1452.64 h60
  text "CERTIFICATION:" at 10147.46,1315.64 h60
  text "MATERIALS AND WORKMANSHIP FOR ALL PCBS" at 10872.46,1315.64 h60
  text "TO MEET OR EXCEED THE REQUIREMENTS OF:" at 10872.46,1217.64 h60
  text "X" at 10498.96,1081.13 h60
  text "ANSI IPC-A-600F CLASS ->" at 10637.96,1081.13 h60
  text "X" at 12277.02,1081.13 h60
  text "2" at 12395.96,1081.14 h60
  text "1" at 12080.96,1079.64 h60
  text "3" at 12749.96,1079.64 h60
  text "X" at 10501.02,921.64 h60
  text "UL 94V-0" at 10637.96,921.64 h60
  text "X" at 11313.02,921.64 h60
  text "RoHS" at 11449.96,921.64 h60
  text "OTHER" at 12094.36,921.64 h60
  text "PER ORDER" at 12491.42,921.64 h60
  text "VIA TENTING:" at 11328,784 h60
  text "ADDITIONAL REQUIREMENTS:" at 10147.46,780.64 h60
  text "X" at 12115,781 h60
  text "YES" at 11899.67,774.92 h60
  text "NO" at 12294.47,774.69 h60
  text "MICROSECTION:" at 10222.23,665.64 h60
  text "YES" at 11127.96,665.64 h60
  text "IMPEDANCE CONTROL:" at 11381,640 h60
  text "YES" at 12349,639 h60
  text "X" at 12907,632 h60
  text "NO" at 12740.47,621.69 h60
  text "REQUIRED" at 11979.46,493.49 h60
  text "BARE BOARD ELEC. TEST:" at 10212.23,490.64 h60
  text "NONE" at 11517.96,490.64 h60
  text "X" at 11852.46,490.64 h60
  text "PER ORDER" at 12571.46,490.64 h60
  text "MANUFACTURER'S UL:" at 10212.23,333.64 h60
  text "RAIL" at 11377.96,329.35 h60
  text "METAL" at 11869.77,329.35 h60
  text "X" at 12245,329 h60
  text "SILK" at 12381.46,329.35 h60
M11 Gerber Information:
  lines w10: -1477,-1535.17 5123,-1535.17 ; -1477,-1331.83 5125,-1331.83 ; -1477,-1128.5 -1477,-1738.5 2528,-1738.5 5125,-1738.5 5125,-1128.5 -1476.5,-1128.5 -1476.5,-1738.5 99,-1738.5 ; 988,-1738.5 988,-1128.5 ; 2255,-1331.83 2255,-1128.5 ; 3095,-1331.83 3095,-1128.5 ; 3717,-1745 3717,-1542.17
  text "ALL ARTWORK VIEWED FROM TOP SIDE" at -1413.5,-1260.67 h60
  text "BOARD #:" at 1063,-1260.67 h60
  text ".prj_number" at 1523,-1261 h60
  text "REV:" at 2453,-1260.67 h60
  text ".PCB_Rev" at 2744.5,-1260.67 h60
  text "SVN REV:" at 3291,-1260.67 h60
  text ".VersionControl_RevNumber" at 3797,-1260.67 h60
  text "LAYER NAME =" at -1413.5,-1463.49 h60
  text "PLOT NAME =" at -1413.5,-1669.34 h60
  text ".plot_File_Name" at -608,-1669.34 h60
  text "GENERATED    :" at 1065,-1669.34 h60
  text ".Print_Date" at 1934.5,-1669.34 h60
  text ".Print_Time" at 2663.5,-1669.34 h60
  text "TEXAS INSTRUMENTS" at 3928,-1669.34 h60
M12 Stackup:
  lines w6: 10093,7072.75 13025,7072.75 ; 10093,7185.35 13025,7185.35 ; 10033,6364 ccw(c10069,6364) 10069,6328 13049,6328 ccw(c13049,6364) 13085,6364 13085,7281 ccw(c13049,7281) 13049,7317 10069,7317 ccw(c10069,7281) 10033,7281 10033,6364
  text "Layer Stack Up Detail for: TIDA-00448_E3.PcbDoc" at 10093,7214.17 h50
  text "Layer" at 10093,7143.35 h26
  text "Gerber" at 11118.14,7143.35 h26
  text "Copper" at 11797.52,7143.35 h26
  text "Dielectric" at 12519.35,7143.35 h26
  text "Name" at 10093,7091.35 h26
  text "Document" at 11118.14,7091.35 h26
  text "Thickness" at 11797.52,7091.35 h26
  text "Material" at 12519.35,7091.35 h26
  text "Top Solder Mask" at 10093,7018.24 h36
  text "(.GTS)" at 11118.14,7018.24 h36
  text "Solder Resist" at 12519.35,7018.24 h36
  text "Top Layer" at 10093,6915.22 h36
  text "(.GTL)" at 11118.14,6915.22 h36
  text "1.4mil" at 11797.52,6915.22 h36
  text "FR-4 High Tg" at 12519.35,6863.71 h36
  text "MidLayer1" at 10093,6812.2 h36
  text "(.G1)" at 11118.14,6812.2 h36
  text "1.4mil" at 11797.52,6812.2 h36
  text "FR-4 High Tg" at 12519.35,6760.69 h36
  text "MidLayer2" at 10093,6709.18 h36
  text "(.G2)" at 11118.14,6709.18 h36
  text "1.4mil" at 11797.52,6709.18 h36
  text "FR-4 High Tg" at 12519.35,6657.67 h36
  text "Bottom Layer" at 10093,6606.16 h36
  text "(.GBL)" at 11118.14,6606.16 h36
  text "1.4mil" at 11797.52,6606.16 h36
  text "Bottom Solder Mask" at 10093,6503.14 h36
  text "(.GBS)" at 11118.14,6503.14 h36
  text "Solder Resist" at 12519.35,6503.14 h36
M13 Component Bodies Top:
  text ".Layer_Name" at -608,-1463.49 h60
M14 Component Bodies Bottom:
  text ".Layer_Name" at -608,-1463.49 h60
M15 Courtyards Top:
  text ".Layer_Name" at -608,-1463.49 h60
M16 Courtyards Bottom:
  text ".Layer_Name" at -608,-1463.49 h60
Drill Drawing:
  text "Drill Table" at 561,5176 h60
  text ".legend" at 545,3363 h60
  text "DRILL TOLERANCE" at 545,3223 h60
  text "FOR PTH +/- 3MIL" at 544,3118 h60
  text "FOR NPTH +/- 2MIL" at 539,3029 h60
  text "16mil drill:+0/-16mil" at 528,2944 h60
  text "12mil drill:+0/-12mil" at 533,2856 h60
  text "20mil drill:+0/-20mil" at 516,2770 h60
  text ".Layer_Name" at -608,-1463.49 h60

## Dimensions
0,0 to 2125,0 on M2 Board Dimensions
0,0 to 0,2550 on M2 Board Dimensions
